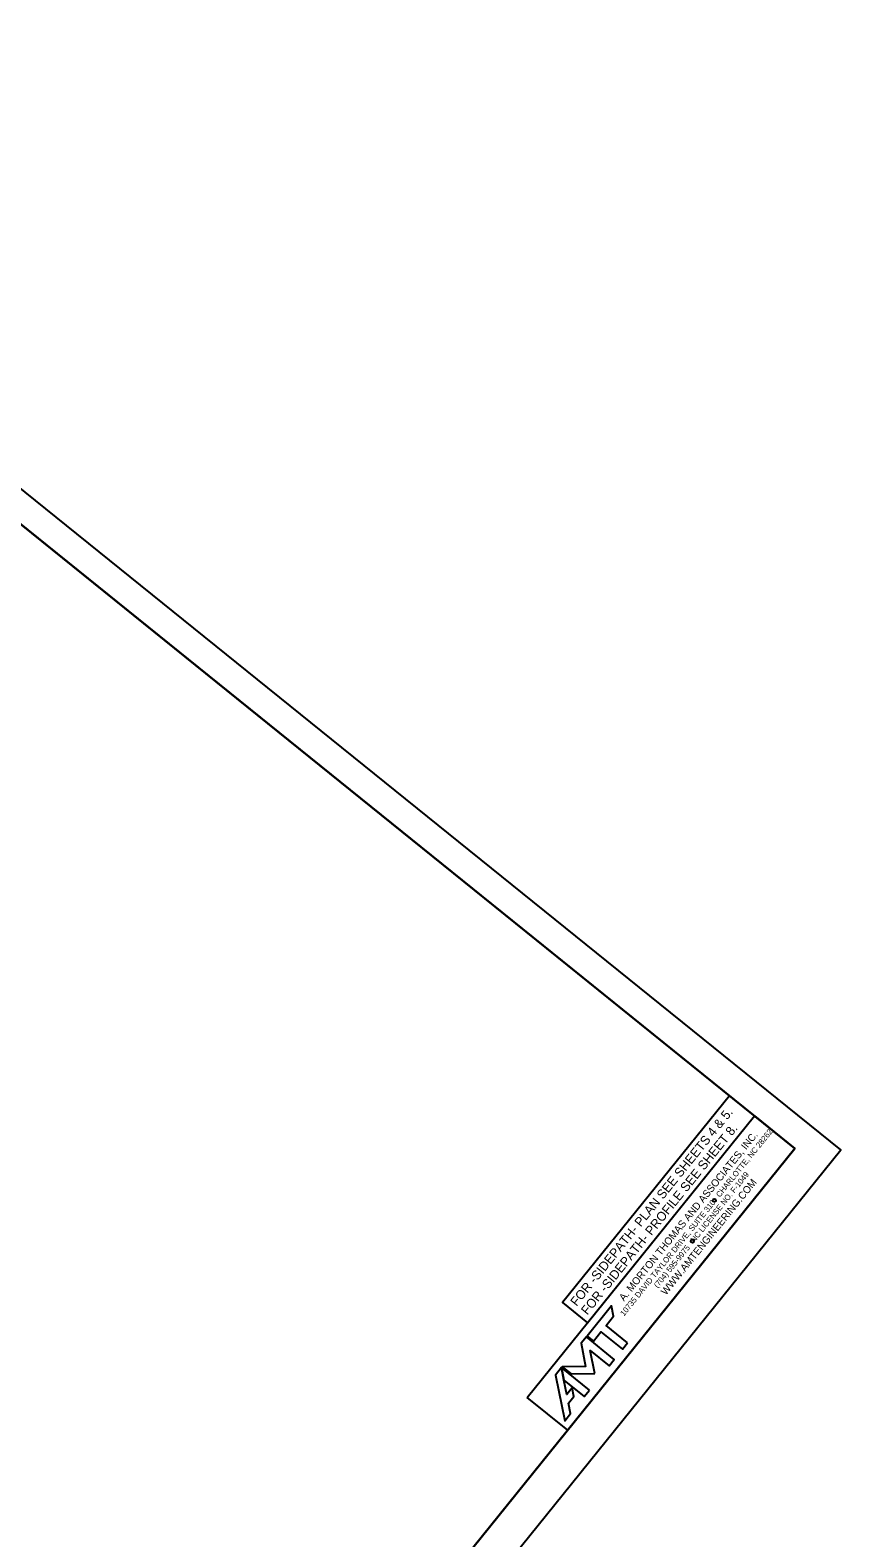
# Model space of a CAD drawing. Extents: x 1487845 to 1489754, y 498370 to 500368.
# Drawn here: x 1489256 to 1489754, y 499442 to 500368 of the extents above; entities that cross this region are included whole.
import ezdxf

# ---------------------------------------------------------------- set-up
doc = ezdxf.new("R2010")
doc.units = 0
for name, color, linetype in [('Prop Grid Mask', 7, 'Continuous'), ('Prop Horizontal Alignment Curve and Spiral Data', 7, 'Continuous'), ('Sheet Block Title CELL', 7, 'Continuous'), ('Sheet Clip Boundary CELL', 7, 'Continuous'), ('Sheet Plan CELL', 7, 'Continuous'), ('Sheet Plot Border Outside CELL', 7, 'Continuous')]:
    doc.layers.add(name, color=color, linetype=linetype)

msp = doc.modelspace()

# ---------------------------------------------------------------- linework, layer by layer
at = {"layer": 'Prop Grid Mask'}
for points in [[(1489598.35, 499574.34), (1489700.77, 499701.35), (1489685.43, 499713.72), (1489583, 499586.72)], [(1489561.39, 499528.52), (1489700.78, 499701.36), (1489725.65, 499681.3), (1489586.27, 499508.46)]]:
    msp.add_lwpolyline(points, close=True, dxfattribs=at)
at = {"layer": 'Sheet Block Title CELL'}
msp.add_lwpolyline([(1489561.39, 499528.52), (1489700.78, 499701.36), (1489725.65, 499681.3), (1489586.27, 499508.46)], close=True, dxfattribs=at)
for points in [[(1489622.97, 499562.01), (1489609.8, 499572.63), (1489614.38, 499578.3), (1489613.1, 499584.74), (1489598.11, 499566.15), (1489602.03, 499562.99), (1489606.64, 499568.71), (1489619.81, 499558.09), (1489622.97, 499562.01)], [(1489602.77, 499543.11), (1489599.96, 499557.35), (1489611.63, 499547.94), (1489614.79, 499551.86), (1489597.7, 499565.65), (1489594.54, 499561.73), (1489597.22, 499547.59), (1489582.9, 499547.29), (1489588.34, 499542.9), (1489602.77, 499543.11)], [(1489583.92, 499539.16), (1489582.49, 499546.78), (1489578.8, 499542.21), (1489584.45, 499514.24), (1489588.02, 499518.67), (1489586.75, 499524.95), (1489590.02, 499529.01), (1489589.04, 499534.41), (1489585.66, 499530.21), (1489583.92, 499539.16)], [(1489599.58, 499533), (1489582.49, 499546.78), (1489583.92, 499539.16), (1489596.42, 499529.08), (1489599.58, 499533)]]:
    msp.add_lwpolyline(points, dxfattribs=at)
for centre in [(1489676.2, 499649.48), (1489662.74, 499624.47)]:
    msp.add_circle(centre, 1, dxfattribs=at)
at = {"layer": 'Sheet Clip Boundary CELL'}
msp.add_lwpolyline([(1488917.84, 500075.78), (1488782.72, 500184.72), (1488048.03, 499273.68), (1488893.23, 498649.1), (1489725.65, 499681.3), (1489043.41, 500231.49)], close=True, dxfattribs=at)
at = {"layer": 'Sheet Plan CELL'}
for points in [[(1488908.33, 500340.46), (1487966.68, 499172.8), (1488784.02, 498513.67), (1489725.65, 499681.3)], [(1488784.02, 498513.67), (1487966.69, 499172.77), (1488782.72, 500184.72), (1488899.54, 500090.53), (1489025.13, 500246.23), (1489725.65, 499681.3)]]:
    msp.add_lwpolyline(points, close=True, dxfattribs=at)
at = {"layer": 'Sheet Plot Border Outside CELL'}
msp.add_lwpolyline([(1488697.03, 498369.94), (1489753.85, 499680.4), (1488901.48, 500367.79), (1487844.66, 499057.32)], close=True, dxfattribs=at)

# ---------------------------------------------------------------- texts
at = {"layer": 'Prop Horizontal Alignment Curve and Spiral Data'}
for s, p in [('FOR -SIDEPATH- PLAN SEE SHEETS 4 & 5.', (1489591.7, 499584.04)), ('FOR -SIDEPATH- PROFILE SEE SHEET 8.', (1489598.26, 499578.74))]:
    msp.add_text(s, height=5.625, rotation=51.11565, dxfattribs=at).set_placement(p)
at = {"layer": 'Sheet Block Title CELL'}
for s, height, p in [('A. MORTON THOMAS AND ASSOCIATES, INC.', 4.5, (1489620.78, 499587.26)), ('10735 DAVID TAYLOR DRIVE, SUITE 310   CHARLOTTE, NC 28262', 3.5, (1489620.8, 499578.13)), ('(704) 595-9975   NC LICENSE NO. F-1049', 3.5, (1489641.45, 499595.37)), ('WWW.AMTENGINEERING.COM', 4.5, (1489646.54, 499590.93))]:
    msp.add_text(s, height=height, rotation=51.11516, dxfattribs=at).set_placement(p)

doc.saveas('drawing.dxf')
